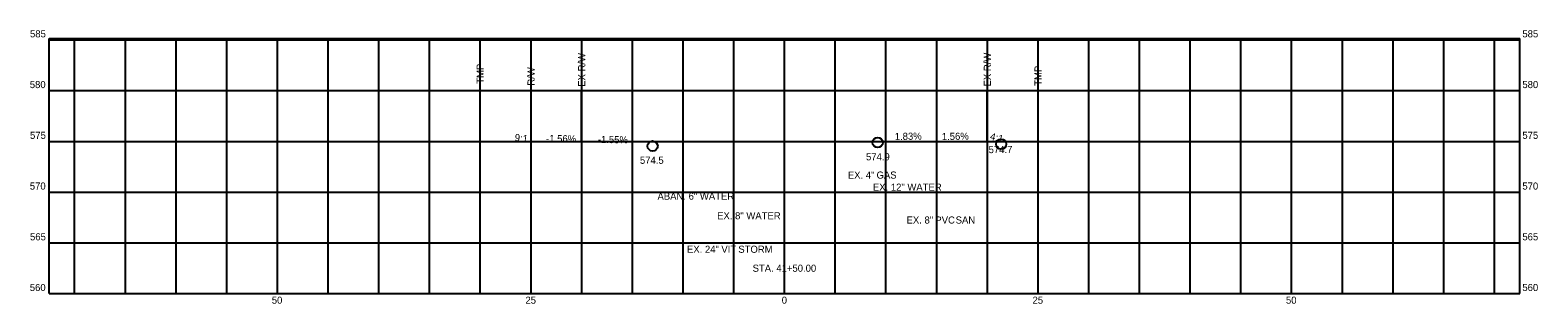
# Model space of a CAD drawing. Extents: x -74 to 74, y 559 to 586.
import ezdxf

# ---------------------------------------------------------------- set-up
doc = ezdxf.new("R2010")
doc.units = 0
for name, color, linetype in [('CM_Corridor_Key_Station', 7, 'Continuous'), ('CM_Corridor_Top_Mesh', 7, 'Continuous'), ('DT_P_Graded_Shoulder', 7, 'Continuous'), ('DT_P_Tie', 7, 'Continuous'), ('MD_P_GRADE_BREAK', 7, 'Continuous'), ('MD_P_Surface_Finished_Grade', 7, 'Continuous'), ('MD_P_Surface_Sidewalk', 7, 'Continuous'), ('MD_P_SW_BOT', 7, 'Continuous'), ('MD_P_SW_TOP', 7, 'Continuous'), ('PV_P_Walk', 7, 'Continuous')]:
    doc.layers.add(name, color=color, linetype=linetype)

msp = doc.modelspace()

# ---------------------------------------------------------------- linework, layer by layer
at = {"layer": 'DT_P_Tie'}
for p, q in [((-20.01, 575.03), (-20.01, 580.03)), ((19.99, 575.06), (19.99, 580.06))]:
    msp.add_line(p, q, dxfattribs=at)
at = {"layer": 'MD_P_GRADE_BREAK'}
for centre in [(9.18, 574.89), (-13.01, 574.54), (21.36, 574.73)]:
    msp.add_circle(centre, 0.5, dxfattribs=at)
at = {"layer": 'MD_P_Surface_Finished_Grade'}
for p, q in [((-30.01, 575.33), (-30.01, 580.33)), ((24.99, 575.13), (24.99, 580.13))]:
    msp.add_line(p, q, dxfattribs=at)
at = {"layer": 'MD_P_SW_TOP'}
for p, q in [((-72.5, 585.13), (72.5, 585.13)), ((-72.5, 560), (-72.5, 585.13)), ((-72.5, 585), (72.5, 585)), ((-70, 560), (-70, 585.13)), ((-65, 560), (-65, 585.13)), ((-60, 560), (-60, 585.13)), ((-55, 560), (-55, 585.13)), ((-50, 560), (-50, 585.13)), ((-45, 560), (-45, 585.13)), ((-40, 560), (-40, 585.13)), ((-35, 560), (-35, 585.13)), ((-30, 560), (-30, 585.13)), ((-25, 560), (-25, 585.13)), ((-20, 560), (-20, 585.13)), ((-15, 560), (-15, 585.13)), ((-10, 560), (-10, 585.13)), ((-5, 560), (-5, 585.13)), ((0, 560), (0, 585.13)), ((5, 560), (5, 585.13)), ((10, 560), (10, 585.13)), ((15, 560), (15, 585.13)), ((20, 560), (20, 585.13)), ((25, 560), (25, 585.13)), ((30, 560), (30, 585.13)), ((35, 560), (35, 585.13)), ((40, 560), (40, 585.13)), ((45, 560), (45, 585.13)), ((50, 560), (50, 585.13)), ((55, 560), (55, 585.13)), ((60, 560), (60, 585.13)), ((65, 560), (65, 585.13)), ((70, 560), (70, 585.13)), ((72.5, 560), (72.5, 585.13)), ((-72.5, 580), (72.5, 580)), ((-72.5, 575), (72.5, 575)), ((-72.5, 570), (72.5, 570)), ((-72.5, 565), (72.5, 565)), ((-72.5, 560), (72.5, 560))]:
    msp.add_line(p, q, dxfattribs=at)
at = {"layer": 'PV_P_Walk'}
msp.add_line((-25, 575.14), (-25, 580.14), dxfattribs=at)

# ---------------------------------------------------------------- texts
at = {"layer": 'CM_Corridor_Key_Station'}
for s, p in [('ABAN. 6" WATER', (-12.53, 569.25)), ('EX. 12" WATER', (8.71, 570.14)), ('EX. 8" WATER', (-6.65, 567.32))]:
    msp.add_text(s, height=0.7, dxfattribs=at).set_placement(p)
at = {"layer": 'CM_Corridor_Top_Mesh'}
for s, p in [('EX. 24"', (-9.62, 564.02)), ('VIT', (-6.23, 564.02)), ('STORM', (-4.56, 564.02))]:
    msp.add_text(s, height=0.7, dxfattribs=at).set_placement(p)
at = {"layer": 'DT_P_Graded_Shoulder'}
for s, p in [('EX. 4"', (6.24, 571.33)), ('GAS', (9.07, 571.33))]:
    msp.add_text(s, height=0.7, dxfattribs=at).set_placement(p)
at = {"layer": 'DT_P_Tie'}
for p in [(-19.66, 580.38), (20.34, 580.41)]:
    msp.add_text('EX R/W', height=0.7, rotation=90, dxfattribs=at).set_placement(p)
at = {"layer": 'MD_P_Surface_Finished_Grade'}
for p in [(-29.66, 580.68), (25.34, 580.48)]:
    msp.add_text('TMP', height=0.7, rotation=90, dxfattribs=at).set_placement(p)
at = {"layer": 'MD_P_Surface_Sidewalk'}
for s, p in [('EX. 8"', (12.03, 566.9)), ('PVC', (14.87, 566.9)), ('SAN', (16.87, 566.9))]:
    msp.add_text(s, height=0.7, dxfattribs=at).set_placement(p)
at = {"layer": 'MD_P_SW_BOT'}
for s, p in [('585', (-74.4, 585.25)), ('585', (72.75, 585.25)), ('580', (-74.42, 580.25)), ('580', (72.75, 580.25)), ('575', (-74.4, 575.25)), ('575', (72.75, 575.25)), ('574.9', (8.03, 573.13)), ('574.7', (20.12, 573.84)), ('574.5', (-14.26, 572.79)), ('570', (-74.42, 570.25)), ('570', (72.75, 570.25)), ('565', (-74.4, 565.25)), ('565', (72.75, 565.25)), ('STA. 41+50.00', (-3.15, 562.15)), ('560', (-74.42, 560.25)), ('560', (72.75, 560.25)), ('50', (-50.56, 559)), ('25', (-25.55, 559)), ('0', (-0.28, 559)), ('25', (24.45, 559)), ('50', (49.44, 559))]:
    msp.add_text(s, height=0.7, dxfattribs=at).set_placement(p)
for s, rotation, p in [('9:1', 353.321, (-26.64, 575.05)), ('-1.56%', 359.1062, (-23.52, 574.94)), ('-1.55%', 359.1123, (-18.42, 574.85)), ('1.83%', 1.0473, (10.87, 575.13)), ('1.56%', 0.8956, (15.51, 575.13)), ('4:1', 345.9656, (20.21, 575.19))]:
    msp.add_text(s, height=0.7, rotation=rotation, dxfattribs=at).set_placement(p)
at = {"layer": 'PV_P_Walk'}
msp.add_text('R/W', height=0.7, rotation=90, dxfattribs=at).set_placement((-24.65, 580.49))

doc.saveas('drawing.dxf')
